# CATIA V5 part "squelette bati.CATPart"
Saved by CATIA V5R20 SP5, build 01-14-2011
Part number: squelette bati
Publications: "Point.1"
Bounding box of the stored display mesh (mm): x -20 to 0, y 0 to 20, z 0 to 0
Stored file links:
  F:\projet\yyang_IAO\squelette bati.CATPart
  F:\projet\yyang_IAO\iao.CATProduct
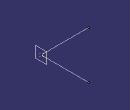
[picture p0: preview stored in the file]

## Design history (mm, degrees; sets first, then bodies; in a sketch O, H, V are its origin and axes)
Set1
  Point1: linked copy from another document
  Plane1: linked copy from another document
Body1 (main body)
  Point2: (0, 0, 0), relative to Point1
  Plane2: type Offset, RefPlane Plane1, Offset 0
  Line1: type PtDir, RefPoint Point1, Direction (1, 0, 0), Start 0, End 20
  Line2: type PtDir, RefPoint Point1, Direction (0, 1, 0), Start 0, End 20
